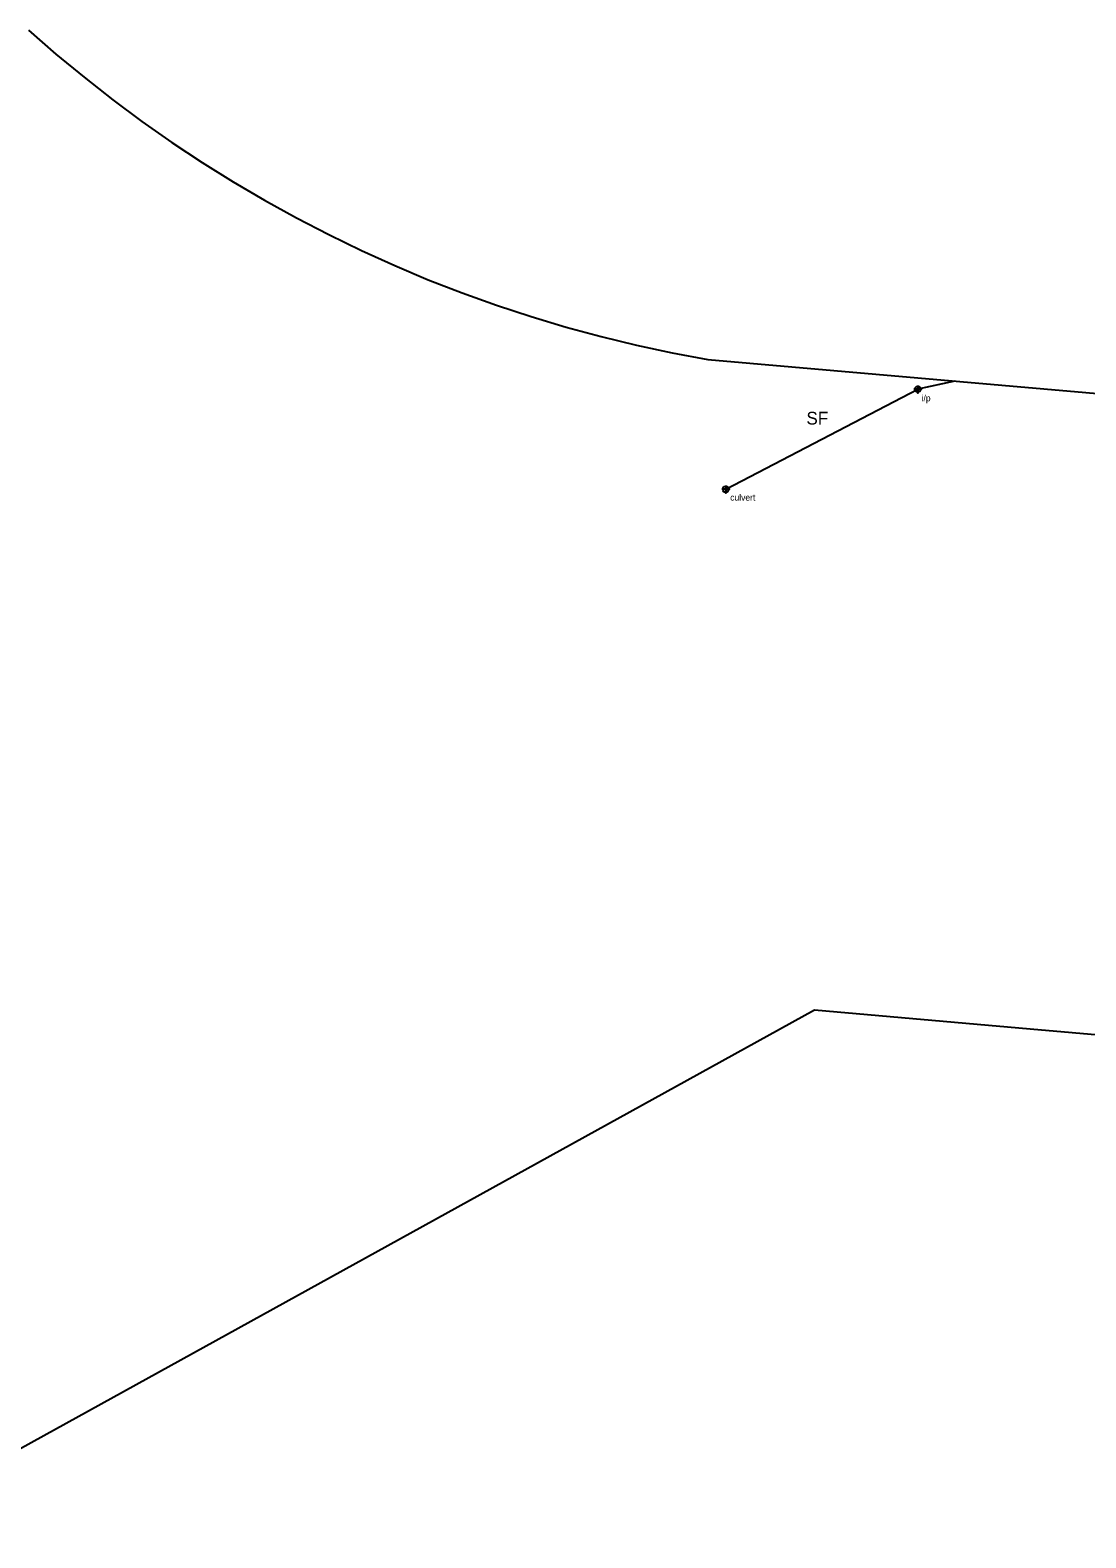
# Model space of a CAD drawing. Extents: x 1637473 to 1644249, y 841388 to 844031.
# Drawn here: x 1642592 to 1643421, y 841547 to 842729 of the extents above; entities that cross this region are included whole.
import ezdxf

# ---------------------------------------------------------------- set-up
doc = ezdxf.new("R2010")
doc.units = 0
for name, color, linetype in [('Default', 7, 'Continuous'), ('Exist Hydro Jurisdictional Stream or Body of Water Mitigable', 7, 'Continuous'), ('Exist Hydro Jurisdictional Stream or Body of Water Mitigable Cogo Number', 7, 'Continuous'), ('Exist Hydro Jurisdictional Stream or Body of Water Mitigable Cogo Point CELL', 7, 'Continuous'), ('Exist Hydro Jurisdictional Stream or Body of Water Mitigable Text', 7, 'Continuous')]:
    doc.layers.add(name, color=color, linetype=linetype)

msp = doc.modelspace()

# ---------------------------------------------------------------- linework, layer by layer
at = {"layer": 'Default'}
for points in [[(1642590.7, 842729.3), (1642612.2, 842710.5), (1642634.3, 842692.3), (1642656.8, 842674.6), (1642679.7, 842657.6), (1642703.1, 842641.2), (1642727, 842625.4), (1642751.2, 842610.3), (1642775.9, 842595.8), (1642800.9, 842582), (1642826.3, 842568.9), (1642852, 842556.4), (1642878.1, 842544.6), (1642904.4, 842533.5), (1642931.1, 842523.2), (1642958, 842513.5), (1642985.1, 842504.6), (1643012.5, 842496.4), (1643040.1, 842488.9), (1643067.9, 842482.1), (1643095.8, 842476.1), (1643123.9, 842470.9), (1643420.4, 842445), (1644249.1, 842372.6)], [(1644203.7, 841873.4), (1643376.8, 841945.6), (1643207.5, 841960.4), (1642457.5, 841546.6)]]:
    msp.add_lwpolyline(points, dxfattribs=at)
at = {"layer": 'Exist Hydro Jurisdictional Stream or Body of Water Mitigable'}
for p in [(1643317.7, 842454), (1643137.9, 842369.1)]:
    msp.add_line(p, (1643288.6, 842447.6), dxfattribs=at)
at = {"layer": 'Exist Hydro Jurisdictional Stream or Body of Water Mitigable Cogo Point CELL'}
for points in [[(1643288.6, 842450.6), (1643288.6, 842444.6), (1643288.6, 842447.6), (1643291.6, 842447.6), (1643285.6, 842447.6)], [(1643137.9, 842372.1), (1643137.9, 842366.1), (1643137.9, 842369.1), (1643140.9, 842369.1), (1643134.9, 842369.1)]]:
    msp.add_lwpolyline(points, dxfattribs=at)
for centre in [(1643288.6, 842447.6), (1643137.9, 842369.1)]:
    msp.add_circle(centre, 2.34, dxfattribs=at)

# ---------------------------------------------------------------- texts
at = {"layer": 'Exist Hydro Jurisdictional Stream or Body of Water Mitigable Cogo Number'}
for s, p in [('i/p', (1643291.6, 842438.1)), ('culvert', (1643141.4, 842360.2))]:
    msp.add_text(s, height=5, dxfattribs=at).set_placement(p)
at = {"layer": 'Exist Hydro Jurisdictional Stream or Body of Water Mitigable Text'}
msp.add_text('SF', height=10, dxfattribs=at).set_placement((1643201.2, 842419.9))

doc.saveas('drawing.dxf')
